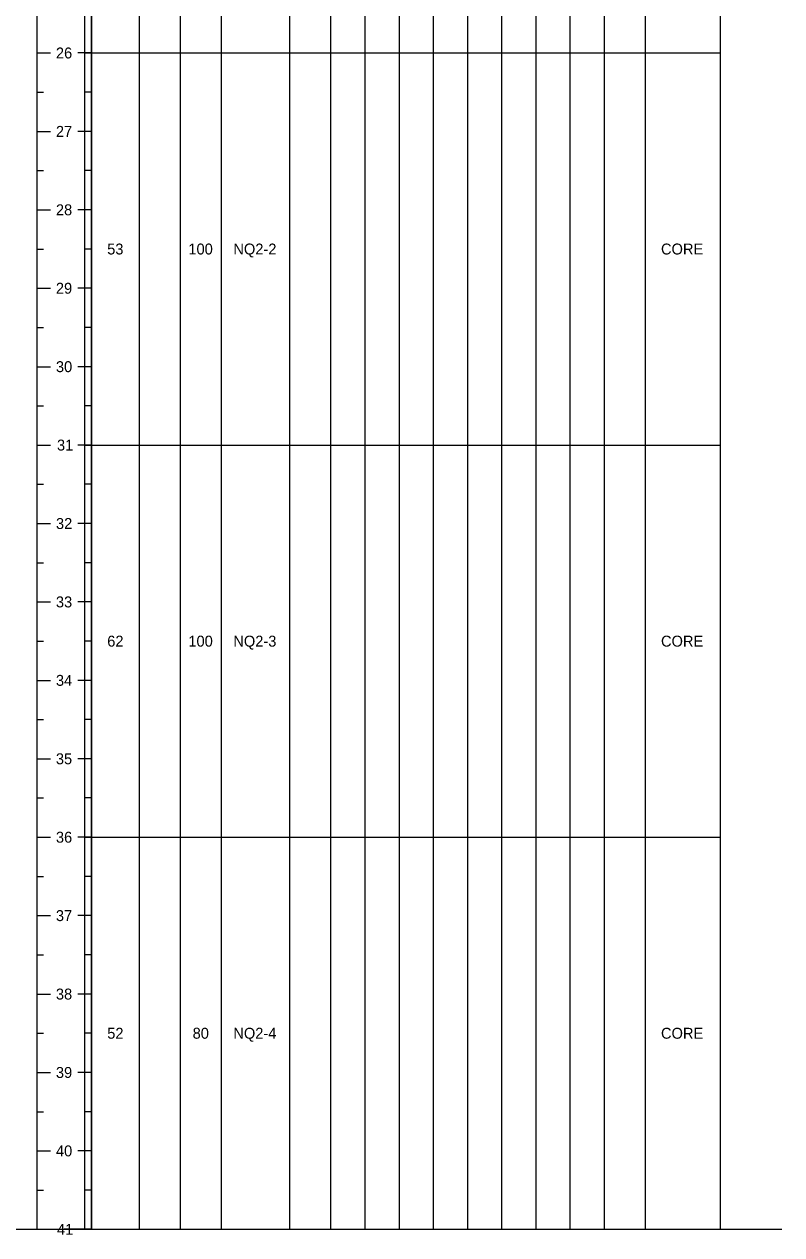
# Model space of a CAD drawing. Extents: x -0.01 to 0.83, y -0.77 to 1.27.
# Drawn here: x 0.372 to 0.833, y -0.769 to -0.03 of the extents above; entities that cross this region are included whole.
import ezdxf

# ---------------------------------------------------------------- set-up
doc = ezdxf.new("R2010")
doc.units = 0

msp = doc.modelspace()

# ---------------------------------------------------------------- linework, layer by layer
for points in [[(0.4125, 1.22083), (0.4125, -0.76533)], [(0.4125, 1.22083), (0.4125, -0.76533)], [(0.44167, 1.22083), (0.44167, -0.76533)], [(0.46667, 1.22083), (0.46667, -0.76533)], [(0.49167, 1.22083), (0.49167, -0.76533)], [(0.53333, 1.22083), (0.53333, -0.76533)], [(0.55833, 1.22083), (0.55833, -0.76533)], [(0.6625, 1.22083), (0.6625, -0.76533)], [(0.725, 1.22083), (0.725, -0.76533)], [(0.75, 1.22083), (0.75, -0.76533)], [(0.75, 1.22083), (0.75, -0.76533)], [(0.79583, 1.22083), (0.79583, -0.76533)], [(0.57917, 1.20833), (0.57917, -0.76533)], [(0.6, 1.20833), (0.6, -0.76533)], [(0.62083, 1.20833), (0.62083, -0.76533)], [(0.64167, 1.20833), (0.64167, -0.76533)], [(0.68333, 1.20833), (0.68333, -0.76533)], [(0.70417, 1.20833), (0.70417, -0.76533)], [(0.725, 1.20833), (0.725, -0.76533)], [(0.37917, 1.19583), (0.37917, -0.76533)], [(0.40833, 0), (0.40833, -0.04783)], [(0.37917, -0.04783), (0.3875, -0.04783)], [(0.37917, -0.04783), (0.38333, -0.04783)], [(0.4125, -0.04783), (0.40417, -0.04783)], [(0.40833, -0.04783), (0.4125, -0.04783)], [(0.40833, -0.04783), (0.40833, -0.287)], [(0.40833, -0.04783), (0.4125, -0.04783)], [(0.4125, -0.04783), (0.40833, -0.04783)], [(0.4125, -0.04783), (0.44167, -0.04783)], [(0.44167, -0.04783), (0.46667, -0.04783)], [(0.46667, -0.04783), (0.49167, -0.04783)], [(0.49167, -0.04783), (0.53333, -0.04783)], [(0.53333, -0.04783), (0.55833, -0.04783)], [(0.55833, -0.04783), (0.57917, -0.04783)], [(0.57917, -0.04783), (0.6, -0.04783)], [(0.6, -0.04783), (0.62083, -0.04783)], [(0.62083, -0.04783), (0.64167, -0.04783)], [(0.64167, -0.04783), (0.6625, -0.04783)], [(0.6625, -0.04783), (0.68333, -0.04783)], [(0.68333, -0.04783), (0.70417, -0.04783)], [(0.70417, -0.04783), (0.725, -0.04783)], [(0.725, -0.04783), (0.75, -0.04783)], [(0.75, -0.04783), (0.79583, -0.04783)], [(0.37917, -0.07175), (0.38333, -0.07175)], [(0.4125, -0.07175), (0.40833, -0.07175)], [(0.37917, -0.09567), (0.3875, -0.09567)], [(0.37917, -0.09567), (0.38333, -0.09567)], [(0.4125, -0.09567), (0.40417, -0.09567)], [(0.4125, -0.09567), (0.40833, -0.09567)], [(0.37917, -0.11958), (0.38333, -0.11958)], [(0.4125, -0.11958), (0.40833, -0.11958)], [(0.37917, -0.1435), (0.3875, -0.1435)], [(0.37917, -0.1435), (0.38333, -0.1435)], [(0.4125, -0.1435), (0.40417, -0.1435)], [(0.4125, -0.1435), (0.40833, -0.1435)], [(0.37917, -0.16742), (0.38333, -0.16742)], [(0.4125, -0.16742), (0.40833, -0.16742)], [(0.37917, -0.19133), (0.3875, -0.19133)], [(0.37917, -0.19133), (0.38333, -0.19133)], [(0.4125, -0.19133), (0.40417, -0.19133)], [(0.4125, -0.19133), (0.40833, -0.19133)], [(0.37917, -0.21525), (0.38333, -0.21525)], [(0.4125, -0.21525), (0.40833, -0.21525)], [(0.37917, -0.23917), (0.3875, -0.23917)], [(0.37917, -0.23917), (0.38333, -0.23917)], [(0.4125, -0.23917), (0.40417, -0.23917)], [(0.4125, -0.23917), (0.40833, -0.23917)], [(0.37917, -0.26308), (0.38333, -0.26308)], [(0.4125, -0.26308), (0.40833, -0.26308)], [(0.37917, -0.287), (0.3875, -0.287)], [(0.37917, -0.287), (0.38333, -0.287)], [(0.4125, -0.287), (0.40417, -0.287)], [(0.40833, -0.287), (0.4125, -0.287)], [(0.40833, -0.287), (0.40833, -0.52617)], [(0.40833, -0.287), (0.4125, -0.287)], [(0.4125, -0.287), (0.40833, -0.287)], [(0.4125, -0.287), (0.44167, -0.287)], [(0.44167, -0.287), (0.46667, -0.287)], [(0.46667, -0.287), (0.49167, -0.287)], [(0.49167, -0.287), (0.53333, -0.287)], [(0.53333, -0.287), (0.55833, -0.287)], [(0.55833, -0.287), (0.57917, -0.287)], [(0.57917, -0.287), (0.6, -0.287)], [(0.6, -0.287), (0.62083, -0.287)], [(0.62083, -0.287), (0.64167, -0.287)], [(0.64167, -0.287), (0.6625, -0.287)], [(0.6625, -0.287), (0.68333, -0.287)], [(0.68333, -0.287), (0.70417, -0.287)], [(0.70417, -0.287), (0.725, -0.287)], [(0.725, -0.287), (0.75, -0.287)], [(0.75, -0.287), (0.79583, -0.287)], [(0.37917, -0.31092), (0.38333, -0.31092)], [(0.4125, -0.31092), (0.40833, -0.31092)], [(0.37917, -0.33483), (0.3875, -0.33483)], [(0.37917, -0.33483), (0.38333, -0.33483)], [(0.4125, -0.33483), (0.40417, -0.33483)], [(0.4125, -0.33483), (0.40833, -0.33483)], [(0.37917, -0.35875), (0.38333, -0.35875)], [(0.4125, -0.35875), (0.40833, -0.35875)], [(0.37917, -0.38267), (0.3875, -0.38267)], [(0.37917, -0.38267), (0.38333, -0.38267)], [(0.4125, -0.38267), (0.40417, -0.38267)], [(0.4125, -0.38267), (0.40833, -0.38267)], [(0.37917, -0.40658), (0.38333, -0.40658)], [(0.4125, -0.40658), (0.40833, -0.40658)], [(0.37917, -0.4305), (0.3875, -0.4305)], [(0.37917, -0.4305), (0.38333, -0.4305)], [(0.4125, -0.4305), (0.40417, -0.4305)], [(0.4125, -0.4305), (0.40833, -0.4305)], [(0.37917, -0.45442), (0.38333, -0.45442)], [(0.4125, -0.45442), (0.40833, -0.45442)], [(0.37917, -0.47833), (0.3875, -0.47833)], [(0.37917, -0.47833), (0.38333, -0.47833)], [(0.4125, -0.47833), (0.40417, -0.47833)], [(0.4125, -0.47833), (0.40833, -0.47833)], [(0.37917, -0.50225), (0.38333, -0.50225)], [(0.4125, -0.50225), (0.40833, -0.50225)], [(0.37917, -0.52617), (0.3875, -0.52617)], [(0.37917, -0.52617), (0.38333, -0.52617)], [(0.4125, -0.52617), (0.40417, -0.52617)], [(0.40833, -0.52617), (0.4125, -0.52617)], [(0.40833, -0.52617), (0.40833, -0.76533)], [(0.40833, -0.52617), (0.4125, -0.52617)], [(0.4125, -0.52617), (0.40833, -0.52617)], [(0.4125, -0.52617), (0.44167, -0.52617)], [(0.44167, -0.52617), (0.46667, -0.52617)], [(0.46667, -0.52617), (0.49167, -0.52617)], [(0.49167, -0.52617), (0.53333, -0.52617)], [(0.53333, -0.52617), (0.55833, -0.52617)], [(0.55833, -0.52617), (0.57917, -0.52617)], [(0.57917, -0.52617), (0.6, -0.52617)], [(0.6, -0.52617), (0.62083, -0.52617)], [(0.62083, -0.52617), (0.64167, -0.52617)], [(0.64167, -0.52617), (0.6625, -0.52617)], [(0.6625, -0.52617), (0.68333, -0.52617)], [(0.68333, -0.52617), (0.70417, -0.52617)], [(0.70417, -0.52617), (0.725, -0.52617)], [(0.725, -0.52617), (0.75, -0.52617)], [(0.75, -0.52617), (0.79583, -0.52617)], [(0.37917, -0.55008), (0.38333, -0.55008)], [(0.4125, -0.55008), (0.40833, -0.55008)], [(0.37917, -0.574), (0.3875, -0.574)], [(0.37917, -0.574), (0.38333, -0.574)], [(0.4125, -0.574), (0.40417, -0.574)], [(0.4125, -0.574), (0.40833, -0.574)], [(0.37917, -0.59792), (0.38333, -0.59792)], [(0.4125, -0.59792), (0.40833, -0.59792)], [(0.37917, -0.62183), (0.3875, -0.62183)], [(0.37917, -0.62183), (0.38333, -0.62183)], [(0.4125, -0.62183), (0.40417, -0.62183)], [(0.4125, -0.62183), (0.40833, -0.62183)], [(0.37917, -0.64575), (0.38333, -0.64575)], [(0.4125, -0.64575), (0.40833, -0.64575)], [(0.37917, -0.66967), (0.3875, -0.66967)], [(0.37917, -0.66967), (0.38333, -0.66967)], [(0.4125, -0.66967), (0.40417, -0.66967)], [(0.4125, -0.66967), (0.40833, -0.66967)], [(0.37917, -0.69358), (0.38333, -0.69358)], [(0.4125, -0.69358), (0.40833, -0.69358)], [(0.37917, -0.7175), (0.3875, -0.7175)], [(0.37917, -0.7175), (0.38333, -0.7175)], [(0.4125, -0.7175), (0.40417, -0.7175)], [(0.4125, -0.7175), (0.40833, -0.7175)], [(0.37917, -0.74142), (0.38333, -0.74142)], [(0.4125, -0.74142), (0.40833, -0.74142)], [(0.33333, -0.76533), (0.37917, -0.76533)], [(0.37917, -0.76533), (0.4125, -0.76533)], [(0.37917, -0.76533), (0.3875, -0.76533)], [(0.37917, -0.76533), (0.38333, -0.76533)], [(0.37917, -0.76533), (0.39583, -0.76533)], [(0.4125, -0.76533), (0.39583, -0.76533)], [(0.4125, -0.76533), (0.40417, -0.76533)], [(0.40833, -0.76533), (0.4125, -0.76533)], [(0.40833, -0.76533), (0.4125, -0.76533)], [(0.4125, -0.76533), (0.40833, -0.76533)], [(0.4125, -0.76533), (0.44167, -0.76533)], [(0.44167, -0.76533), (0.46667, -0.76533)], [(0.46667, -0.76533), (0.49167, -0.76533)], [(0.49167, -0.76533), (0.53333, -0.76533)], [(0.53333, -0.76533), (0.55833, -0.76533)], [(0.55833, -0.76533), (0.57917, -0.76533)], [(0.57917, -0.76533), (0.6, -0.76533)], [(0.6, -0.76533), (0.62083, -0.76533)], [(0.62083, -0.76533), (0.64167, -0.76533)], [(0.64167, -0.76533), (0.6625, -0.76533)], [(0.6625, -0.76533), (0.68333, -0.76533)], [(0.68333, -0.76533), (0.70417, -0.76533)], [(0.70417, -0.76533), (0.725, -0.76533)], [(0.725, -0.76533), (0.75, -0.76533)], [(0.75, -0.76533), (0.79583, -0.76533)], [(0.79583, -0.76533), (0.83333, -0.76533)]]:
    msp.add_lwpolyline(points)
for points in [[(0.40833, -0.04783), (0.4125, -0.04783), (0.4125, 0), (0.40833, 0)], [(0.40833, -0.287), (0.4125, -0.287), (0.4125, -0.04783), (0.40833, -0.04783)], [(0.40833, -0.52617), (0.4125, -0.52617), (0.4125, -0.287), (0.40833, -0.287)], [(0.40833, -0.76533), (0.4125, -0.76533), (0.4125, -0.52617), (0.40833, -0.52617)]]:
    msp.add_lwpolyline(points, close=True)

# ---------------------------------------------------------------- texts
for s, p in [('26', (0.39087, -0.05117)), ('27', (0.39087, -0.099)), ('28', (0.39086, -0.14683)), ('53', (0.42212, -0.17075)), ('100', (0.47162, -0.17075)), ('NQ2-2', (0.49903, -0.17075)), ('CORE', (0.75971, -0.17075)), ('29', (0.39086, -0.19467)), ('30', (0.39088, -0.2425)), ('31', (0.39151, -0.29033)), ('32', (0.3909, -0.33817)), ('33', (0.39087, -0.386)), ('62', (0.42215, -0.40992)), ('100', (0.47162, -0.40992)), ('NQ2-3', (0.499, -0.40992)), ('CORE', (0.75971, -0.40992)), ('34', (0.39088, -0.43383)), ('35', (0.39084, -0.48167)), ('36', (0.39087, -0.5295)), ('37', (0.39087, -0.57733)), ('38', (0.39086, -0.62517)), ('52', (0.42215, -0.64908)), ('80', (0.47421, -0.64908)), ('NQ2-4', (0.49901, -0.64908)), ('CORE', (0.75971, -0.64908)), ('39', (0.39086, -0.673)), ('40', (0.39088, -0.72083)), ('41', (0.39151, -0.76867))]:
    msp.add_text(s, height=0.006667).set_placement(p)

doc.saveas('drawing.dxf')
